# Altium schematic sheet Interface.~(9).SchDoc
size A4
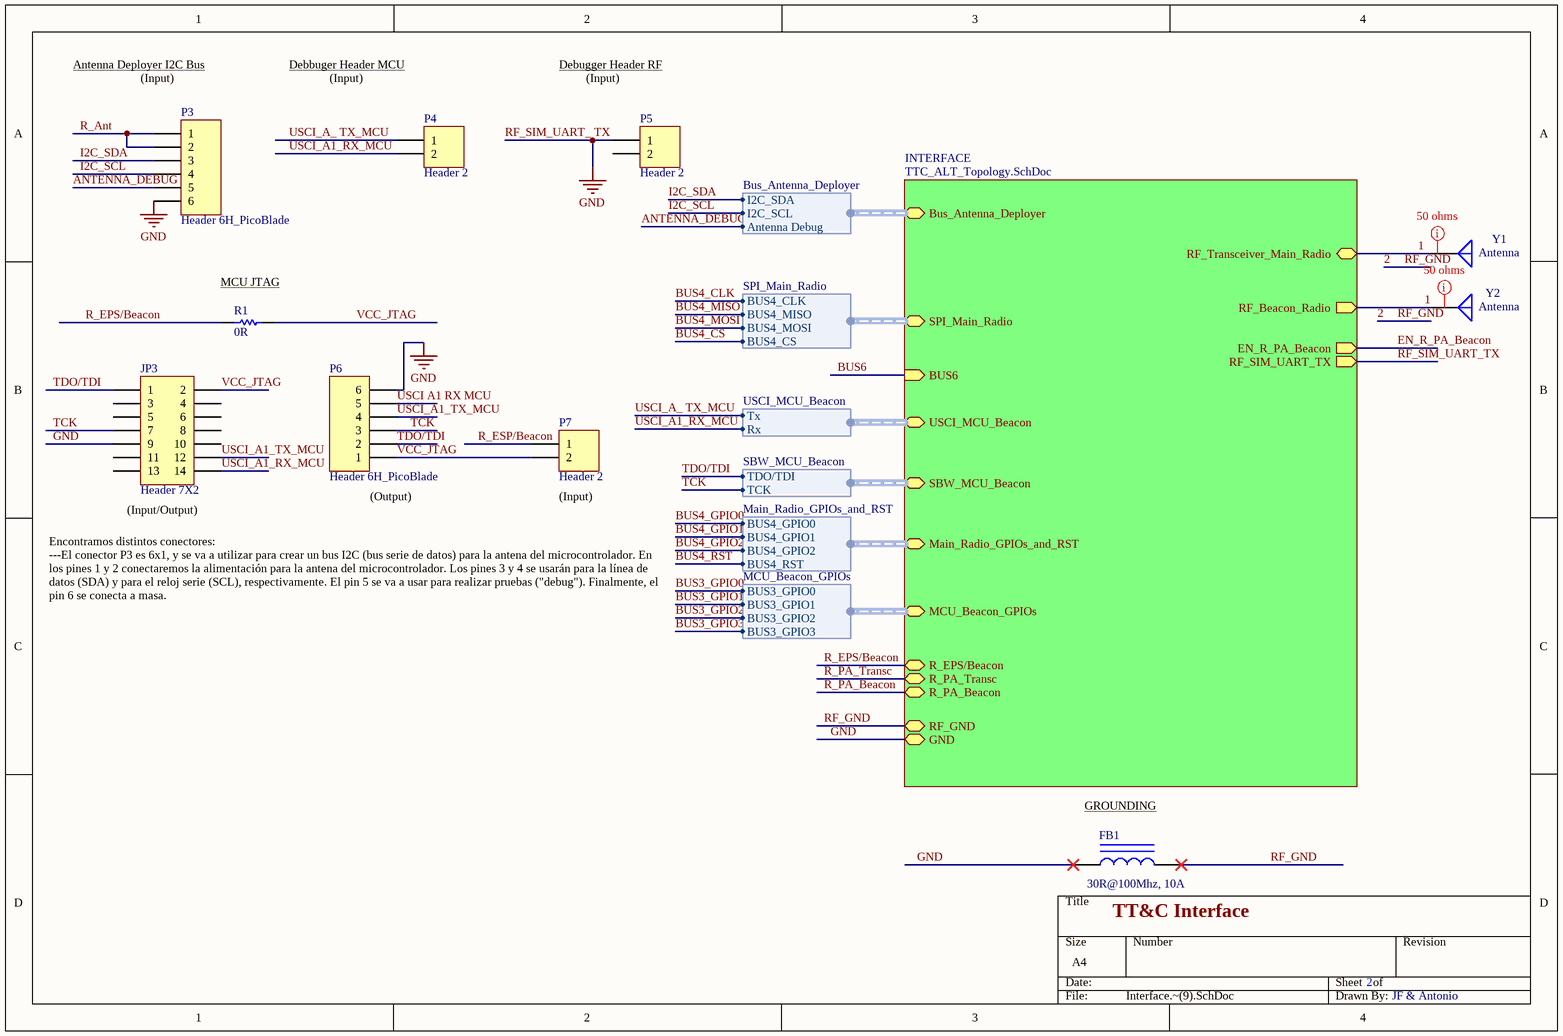
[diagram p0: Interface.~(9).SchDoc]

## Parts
FB1  value 30R@100Mhz, 10A  [INDC3216]
JP3  Header 7X2  [HDR2X7]
P3  Header 6H_PicoBlade  [HDR1X6H]
P4  Header 2  [HDR1X2]
P5  Header 2  [HDR1X2]
P6  Header 6H_PicoBlade  [HDR1X6H]
P7  Header 2  [HDR1X2]
R1  0R  [R]
Y1  Antenna  [PIN1]
Y2  Antenna  [PIN1]

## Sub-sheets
INTERFACE = TTC_ALT_Topology.SchDoc: RF_Transceiver_Main_Radio, RF_Beacon_Radio (out), EN_R_PA_Beacon (out), RF_SIM_UART_TX (out), Bus_Antenna_Deployer (harness Bus_Antenna_Deployer), SPI_Main_Radio (harness SPI_Main_Radio), BUS6 (in), Main_Radio_GPIOs_and_RST (harness Main_Radio_GPIOs_and_RST), USCI_MCU_Beacon (harness USCI_MCU_Beacon), MCU_Beacon_GPIOs (harness MCU_Beacon_GPIOs), R_EPS/Beacon, R_PA_Transc, R_PA_Beacon, RF_GND, GND, SBW_MCU_Beacon (harness SBW_MCU_Beacon)

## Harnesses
Bus_Antenna_Deployer: I2C_SDA, I2C_SCL, Antenna Debug
SPI_Main_Radio: BUS4_CLK, BUS4_MISO, BUS4_MOSI, BUS4_CS
SBW_MCU_Beacon: TDO/TDI, TCK
Main_Radio_GPIOs_and_RST: BUS4_GPIO0, BUS4_GPIO1, BUS4_GPIO2, BUS4_RST
MCU_Beacon_GPIOs: BUS3_GPIO0, BUS3_GPIO1, BUS3_GPIO2, BUS3_GPIO3
USCI_MCU_Beacon: Tx, Rx

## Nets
GND: FB1.1 JP3.9 P3.6 P5.1 P6.6 ; sheet INTERFACE/GND  [also labelled RF_SIM_UART_ TX]
1: Y1.1(A) Y2.1(A) ; sheet INTERFACE/RF_Transceiver_Main_Radio, sheet INTERFACE/RF_Beacon_Radio
2: FB1.2 ; sheet INTERFACE/RF_GND  [also labelled RF_GND]
ANTENNA_DEBUG: P3.5 ; sheet INTERFACE/Bus_Antenna_Deployer.Antenna Debug
I2C_SCL: P3.4 ; sheet INTERFACE/Bus_Antenna_Deployer.I2C_SCL
I2C_SDA: P3.3 ; sheet INTERFACE/Bus_Antenna_Deployer.I2C_SDA
R_Ant: P3.1 P3.2
R_EPS/Beacon: R1.1 ; sheet INTERFACE/R_EPS/Beacon
R_ESP/Beacon: P7.1
TCK: JP3.7 P6.3 ; sheet INTERFACE/SBW_MCU_Beacon.TCK
TDO/TDI: JP3.1 P6.2 ; sheet INTERFACE/SBW_MCU_Beacon.TDO/TDI
USCI A1 RX MCU: P6.5
USCI_A1_RX_MCU: JP3.14 P4.2 ; sheet INTERFACE/USCI_MCU_Beacon.Rx
USCI_A1_TX_MCU: JP3.12 P6.4
USCI_A_ TX_MCU: P4.1 ; sheet INTERFACE/USCI_MCU_Beacon.Tx
VCC_JTAG: JP3.2 P6.1 P7.2 R1.2

Not connected (* = marked no-connect by the designer): JP3 3 4 5 6 8 10 11 13; P5 2

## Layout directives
mark named 50 ohms: (no net found under the mark)

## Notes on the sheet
- Antenna Deployer I2C Bus
- (near P3) (Input)
- Debbuger Header MCU
- (Input)
- Debugger Header RF
- (near R1) MCU JTAG
- (near JP3) (Input/Output)
- (near P6) (Output)
- (near P7) (Input)
- (near FB1) GROUNDING
- (near FB1) TT&C Interface
- Encontramos distintos conectores:
  ---El conector P3 es 6x1, y se va a utilizar para crear un bus I2C (bus serie de datos) para la antena del microcontrolador. En los pines 1 y 2 conectaremos la alimentación para la antena del microcontrolador. Los pines 3 y 4 se usarán para la línea de datos (SDA) y para el reloj serie (SCL), respectivamente. El pin 5 se va a usar para realizar pruebas ("debug"). Finalmente, el pin 6 se conecta a masa.
- 2
- JF & Antonio

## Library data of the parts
FB1 = Inductor Iron: Magnetic-Core Inductor
JP3 = Header 7X2: Header, 7-Pin, Dual row
P3 = Header 6H: Header, 6-Pin, Right Angle
P4 P5 P7 = Header 2: Header, 2-Pin
P6 = Header 6H: Header, 6-Pin, Left Angle
R1 = Res1: Resistor
Y1 Y2 = Antenna: Generic Antenna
